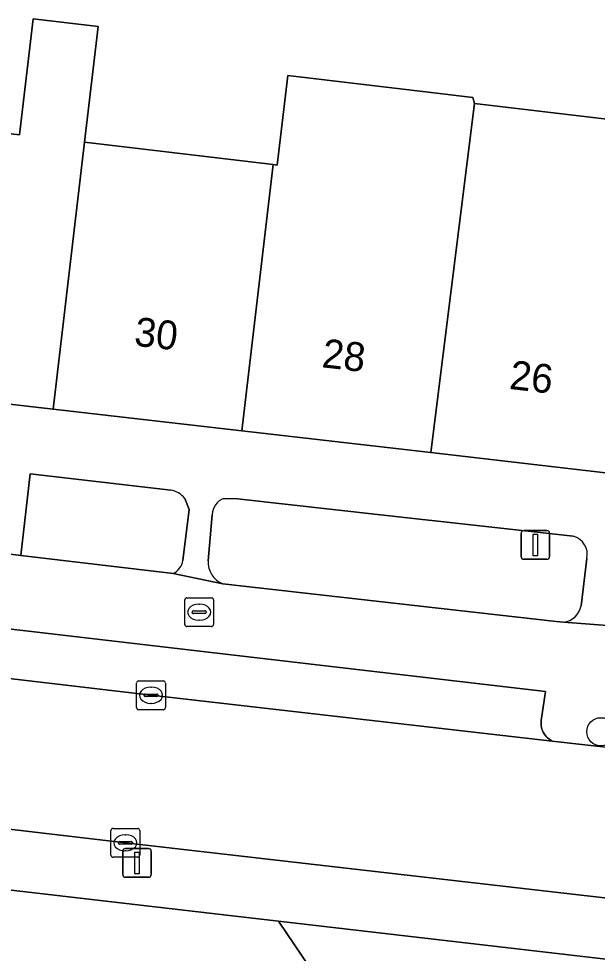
# Model space of a CAD drawing. Extents: x 161692 to 162379, y 380760 to 381678.
# Drawn here: x 162153.91 to 162173.98, y 380911.1 to 380943.5 of the extents above; entities that cross this region are included whole.
import ezdxf

# ---------------------------------------------------------------- set-up
doc = ezdxf.new("R2010")
doc.units = 0
for name, color, linetype in [('IMGEO_Boom', 7, 'Continuous'), ('IMGEO_Erf', 7, 'Continuous'), ('IMGEO_Groenvoorziening', 7, 'Continuous'), ('IMGEO_Kolk', 7, 'Continuous'), ('IMGEO_Lichtmast', 7, 'Continuous'), ('IMGEO_Pand', 7, 'Continuous'), ('IMGEO_Pand_nummerreeks', 7, 'Continuous'), ('IMGEO_Parkeervlak_open', 7, 'Continuous'), ('IMGEO_Rijbaan_lokaal_open', 7, 'Continuous'), ('IMGEO_Rioolput', 7, 'Continuous'), ('IMGEO_Voetpad_open', 7, 'Continuous')]:
    doc.layers.add(name, color=color, linetype=linetype)

msp = doc.modelspace()

# ---------------------------------------------------------------- linework, layer by layer
at = {"layer": 'IMGEO_Boom'}
msp.add_circle((162174.101, 380918.781), 0.489, dxfattribs=at)
at = {"layer": 'IMGEO_Erf'}
msp.add_lwpolyline([(162149.749, 380939.976), (162153.942, 380939.481), (162154.414, 380943.502), (162156.661, 380943.237), (162156.19, 380939.216), (162162.732, 380938.443), (162162.879, 380938.426), (162163.245, 380941.527), (162168.211, 380940.941), (162169.663, 380940.77), (162169.722, 380940.558), (162176.175, 380939.797), (162176.102, 380939.161), (162180.326, 380938.663), (162180.07, 380936.433), (162182.082, 380936.203), (162182.337, 380938.426), (162182.537, 380940.116), (162189.348, 380939.336), (162195.488, 380938.633), (162195.532, 380939.009), (162195.906, 380938.966), (162196.729, 380938.872), (162202.378, 380938.225)], dxfattribs=at)
at = {"layer": 'IMGEO_Groenvoorziening'}
for points in [[(162159.191, 380927.157), (162154.306, 380927.722), (162153.979, 380924.897), (162159.272, 380924.264)], [(162159.824, 380926.485), (162159.671, 380926.871)], [(162173.145, 380925.558), (162166.566, 380926.294), (162161.497, 380926.854), (162161.027, 380926.872)], [(162159.608, 380924.721), (162159.824, 380926.485)], [(162160.624, 380926.307), (162160.485, 380924.708)], [(162173.419, 380923.148), (162173.614, 380924.784)], [(162160.992, 380923.909), (162172.549, 380922.602), (162172.806, 380922.582)], [(162179.111, 380876.785), (162181.716, 380899.182), (162170.889, 380900.442), (162162.923, 380912.217), (162130.514, 380915.971), (162126.267, 380878.692), (162126.199, 380878.375), (162131.289, 380877.654), (162145.584, 380875.831), (162156.037, 380874.407), (162163.634, 380873.357), (162172.879, 380872.08)], [(162176.671, 380910.624), (162162.923, 380912.217), (162170.889, 380900.442), (162181.716, 380899.182), (162182.348, 380904.613), (162180.846, 380904.754), (162180.998, 380906.358)]]:
    msp.add_lwpolyline(points, dxfattribs=at)
for centre, radius, start, end in [((162159.064, 380926.398), 0.77, 37.9348, 80.4894), ((162161.244, 380926.291), 0.62, 110.4868, 178.5146), ((162172.986, 380924.933), 0.645, 346.674, 75.7529), ((162158.962, 380924.844), 0.658, 298.1306, 349.2205), ((162161.285, 380924.656), 0.802, 176.2529, 248.5409), ((162172.731, 380923.278), 0.7, 276.1575, 349.2768)]:
    msp.add_arc(centre, radius, start, end, dxfattribs=at)
at = {"layer": 'IMGEO_Kolk'}
for p, q in [((162158, 380919.62), (162158, 380920.472)), ((162158.075, 380920.546), (162158.927, 380920.546)), ((162159.001, 380920.472), (162159.001, 380919.62)), ((162158.302, 380920.089), (162158.7, 380920.089)), ((162158.488, 380920.326), (162158.513, 380920.326)), ((162158.259, 380920.04), (162158.259, 380920.052)), ((162158.697, 380920.003), (162158.299, 380920.003)), ((162158.511, 380919.766), (162158.486, 380919.766)), ((162158.743, 380920.052), (162158.743, 380920.04)), ((162158.927, 380919.546), (162158.075, 380919.546)), ((162157.11, 380914.505), (162157.11, 380915.357)), ((162157.185, 380915.431), (162158.037, 380915.431)), ((162157.598, 380915.211), (162157.623, 380915.211)), ((162158.111, 380915.357), (162158.111, 380914.505)), ((162157.369, 380914.925), (162157.369, 380914.937)), ((162157.807, 380914.888), (162157.409, 380914.888)), ((162157.412, 380914.974), (162157.81, 380914.974)), ((162157.853, 380914.937), (162157.853, 380914.925)), ((162157.621, 380914.651), (162157.596, 380914.651)), ((162158.037, 380914.431), (162157.185, 380914.431))]:
    msp.add_line(p, q, dxfattribs=at)
for points in [[(162158, 380919.62), (162158, 380920.472)], [(162158.075, 380920.546), (162158.927, 380920.546)], [(162159.001, 380920.472), (162159.001, 380919.62)], [(162158.927, 380919.546), (162158.075, 380919.546)], [(162157.11, 380914.505), (162157.11, 380915.357)], [(162157.185, 380915.431), (162158.037, 380915.431)], [(162158.111, 380915.357), (162158.111, 380914.505)], [(162158.037, 380914.431), (162157.185, 380914.431)]]:
    msp.add_lwpolyline(points, dxfattribs=at)
for centre, radius, start, end in [((162158.077, 380920.47), 0.0765, 91.552, 178.448), ((162158.077, 380920.47), 0.0765, 91.552, 178.448), ((162158.925, 380920.47), 0.0765, 1.552, 88.448), ((162158.925, 380920.47), 0.0765, 1.552, 88.448), ((162158.299, 380920.049), 0.0403, 85.8775, 175.7526), ((162158.704, 380920.051), 0.0386, 1.7309, 96.639), ((162158.296, 380920.039), 0.0366, 178.938, 274.7102), ((162158.7, 380920.046), 0.043, 264.8664, 352.4533), ((162158.077, 380919.622), 0.0765, 181.552, 268.448), ((162158.077, 380919.622), 0.0765, 181.552, 268.448), ((162158.925, 380919.622), 0.0765, 271.552, 358.448), ((162158.925, 380919.622), 0.0765, 271.552, 358.448), ((162157.187, 380915.355), 0.0765, 91.552, 178.448), ((162157.187, 380915.355), 0.0765, 91.552, 178.448), ((162158.035, 380915.355), 0.0765, 1.552, 88.448), ((162158.035, 380915.355), 0.0765, 1.552, 88.448), ((162157.409, 380914.934), 0.0403, 85.8775, 175.7526), ((162157.406, 380914.924), 0.0366, 178.938, 274.7102), ((162157.81, 380914.931), 0.043, 264.8664, 352.4533), ((162157.814, 380914.936), 0.0386, 1.7309, 96.639), ((162157.187, 380914.507), 0.0765, 181.552, 268.448), ((162157.187, 380914.507), 0.0765, 181.552, 268.448), ((162158.035, 380914.507), 0.0765, 271.552, 358.448), ((162158.035, 380914.507), 0.0765, 271.552, 358.448)]:
    msp.add_arc(centre, radius, start, end, dxfattribs=at)
for centre, major_axis, ratio, start_param, end_param in [((162158.487, 380920.046), (-0.387, 0.002), 0.722429, 4.712389, 7.853982), ((162158.512, 380920.046), (-0.39, 0.002), 0.717154, 1.570796, 4.712389), ((162157.597, 380914.931), (-0.387, 0.002), 0.722429, 4.712389, 7.853982), ((162157.622, 380914.931), (-0.39, 0.002), 0.717154, 1.570796, 4.712389)]:
    msp.add_ellipse(centre, major_axis=major_axis, ratio=ratio, start_param=start_param, end_param=end_param, dxfattribs=at)
at = {"layer": 'IMGEO_Lichtmast'}
for p, q in [((162171.334, 380924.86), (162171.334, 380925.66)), ((162171.334, 380925.66), (162171.334, 380924.86)), ((162171.434, 380925.76), (162172.224, 380925.76)), ((162172.224, 380925.76), (162171.434, 380925.76)), ((162172.324, 380925.66), (162172.324, 380924.86)), ((162172.324, 380924.86), (162172.324, 380925.66)), ((162172.224, 380924.76), (162171.434, 380924.76)), ((162171.434, 380924.76), (162172.224, 380924.76)), ((162157.519, 380913.835), (162157.519, 380914.635)), ((162157.519, 380914.635), (162157.519, 380913.835)), ((162157.619, 380914.735), (162158.409, 380914.735)), ((162158.409, 380914.735), (162157.619, 380914.735)), ((162158.509, 380914.635), (162158.509, 380913.835)), ((162158.509, 380913.835), (162158.509, 380914.635)), ((162158.409, 380913.735), (162157.619, 380913.735)), ((162157.619, 380913.735), (162158.409, 380913.735))]:
    msp.add_line(p, q, dxfattribs=at)
for points in [[(162171.754, 380925.635), (162171.904, 380925.635), (162171.904, 380924.885), (162171.754, 380924.885), (162171.754, 380925.635)], [(162157.939, 380914.61), (162158.089, 380914.61), (162158.089, 380913.86), (162157.939, 380913.86), (162157.939, 380914.61)]]:
    msp.add_lwpolyline(points, dxfattribs=at)
for centre, start, end in [((162171.434, 380925.66), 90, 180), ((162171.434, 380925.66), 90, 180), ((162172.224, 380925.66), 0, 90), ((162172.224, 380925.66), 360, 90), ((162171.434, 380924.86), 180, 270), ((162171.434, 380924.86), 180, 270), ((162172.224, 380924.86), 270, 0), ((162172.224, 380924.86), 270, 0), ((162157.619, 380914.635), 90, 180), ((162157.619, 380914.635), 90, 180), ((162158.409, 380914.635), 0, 90), ((162158.409, 380914.635), 360, 90), ((162157.619, 380913.835), 180, 270), ((162157.619, 380913.835), 180, 270), ((162158.409, 380913.835), 270, 0), ((162158.409, 380913.835), 270, 0)]:
    msp.add_arc(centre, 0.1, start, end, dxfattribs=at)
at = {"layer": 'IMGEO_Pand'}
for points in [[(162156.19, 380939.216), (162156.661, 380943.237), (162154.414, 380943.502), (162153.942, 380939.481), (162149.749, 380939.976), (162149.553, 380938.318), (162146.545, 380938.673), (162145.84, 380932.694), (162148.848, 380932.339), (162148.655, 380930.7), (162155.105, 380929.962)], [(162161.646, 380929.214), (162168.105, 380928.475), (162168.21, 380928.463), (162169.722, 380940.558), (162169.663, 380940.77), (162168.211, 380940.941), (162163.245, 380941.527), (162162.879, 380938.426), (162162.732, 380938.443)], [(162176.102, 380939.161), (162176.175, 380939.797), (162169.722, 380940.558), (162168.21, 380928.463), (162174.757, 380927.705)], [(162162.732, 380938.443), (162156.19, 380939.216), (162155.105, 380929.962), (162161.646, 380929.214)]]:
    msp.add_lwpolyline(points, close=True, dxfattribs=at)
at = {"layer": 'IMGEO_Parkeervlak_open'}
msp.add_lwpolyline([(162144.319, 380921.71), (162158.501, 380920.045), (162172.418, 380918.461), (162172.394, 380918.473), (162172.342, 380918.503), (162172.292, 380918.537), (162172.246, 380918.575), (162172.204, 380918.618), (162172.166, 380918.664), (162172.132, 380918.713), (162172.102, 380918.766), (162172.077, 380918.82), (162172.057, 380918.877), (162172.043, 380918.935), (162172.033, 380918.994), (162172.029, 380919.054), (162172.03, 380919.114), (162172.037, 380919.174), (162172.178, 380920.182), (162144.831, 380923.365)], dxfattribs=at)
at = {"layer": 'IMGEO_Rijbaan_lokaal_open'}
for points in [[(162194.36, 380915.961), (162175.911, 380918.063), (162172.418, 380918.461), (162158.501, 380920.045), (162144.319, 380921.71)], [(162140.919, 380916.892), (162157.612, 380914.932), (162177.053, 380912.703), (162177.833, 380912.69), (162193.581, 380910.917), (162194.485, 380910.711), (162194.716, 380910.676), (162208.277, 380908.928), (162208.7, 380908.873), (162217.892, 380907.916), (162227.216, 380906.767), (162227.782, 380906.697), (162234.526, 380905.958), (162239.433, 380906.183), (162250.003, 380907.94), (162251.002, 380908.119), (162251.25, 380908.148), (162253.265, 380908.282), (162255.284, 380908.236), (162255.857, 380913.38), (162254.116, 380913.492)]]:
    msp.add_lwpolyline(points, dxfattribs=at)
at = {"layer": 'IMGEO_Rioolput'}
for p, q in [((162159.67, 380922.501), (162159.67, 380923.353)), ((162159.745, 380923.427), (162160.597, 380923.427)), ((162160.671, 380923.353), (162160.671, 380922.501)), ((162160.158, 380923.207), (162160.183, 380923.207)), ((162159.929, 380922.921), (162159.929, 380922.933)), ((162160.367, 380922.884), (162159.969, 380922.884)), ((162159.972, 380922.97), (162160.37, 380922.97)), ((162160.413, 380922.933), (162160.413, 380922.921)), ((162160.597, 380922.427), (162159.745, 380922.427)), ((162160.181, 380922.647), (162160.156, 380922.647))]:
    msp.add_line(p, q, dxfattribs=at)
for points in [[(162159.67, 380922.501), (162159.67, 380923.353)], [(162159.745, 380923.427), (162160.597, 380923.427)], [(162160.671, 380923.353), (162160.671, 380922.501)], [(162160.597, 380922.427), (162159.745, 380922.427)]]:
    msp.add_lwpolyline(points, dxfattribs=at)
for centre, radius, start, end in [((162159.747, 380923.351), 0.0765, 91.552, 178.448), ((162159.747, 380923.351), 0.0765, 91.552, 178.448), ((162160.595, 380923.351), 0.0765, 1.552, 88.448), ((162160.595, 380923.351), 0.0765, 1.552, 88.448), ((162159.969, 380922.93), 0.0403, 85.8775, 175.7526), ((162159.966, 380922.92), 0.0366, 178.938, 274.7102), ((162160.37, 380922.927), 0.043, 264.8664, 352.4533), ((162160.374, 380922.932), 0.0386, 1.7309, 96.639), ((162159.747, 380922.503), 0.0765, 181.552, 268.448), ((162159.747, 380922.503), 0.0765, 181.552, 268.448), ((162160.595, 380922.503), 0.0765, 271.552, 358.448), ((162160.595, 380922.503), 0.0765, 271.552, 358.448)]:
    msp.add_arc(centre, radius, start, end, dxfattribs=at)
for centre, major_axis, ratio, start_param, end_param in [((162160.157, 380922.927), (-0.387, 0.002), 0.722429, 4.712389, 7.853982), ((162160.182, 380922.927), (-0.39, 0.002), 0.717154, 1.570796, 4.712389)]:
    msp.add_ellipse(centre, major_axis=major_axis, ratio=ratio, start_param=start_param, end_param=end_param, dxfattribs=at)
at = {"layer": 'IMGEO_Voetpad_open'}
for points in [[(162246.079, 380919.46), (162239.67, 380920.198), (162233.283, 380920.934), (162232.951, 380920.972), (162226.693, 380921.696), (162220.458, 380922.418), (162213.812, 380923.186), (162207.219, 380923.949), (162200.781, 380924.694), (162193.937, 380925.486), (162187.797, 380926.197), (162180.993, 380926.984), (162174.757, 380927.705), (162168.21, 380928.463), (162168.105, 380928.475), (162161.646, 380929.214), (162155.105, 380929.962), (162148.655, 380930.7), (162144.778, 380931.153)], [(162145.325, 380928.896), (162147.083, 380928.518), (162149.069, 380928.327), (162153.474, 380927.818), (162153.157, 380924.996), (162153.979, 380924.897), (162154.306, 380927.722), (162159.191, 380927.157)], [(162159.671, 380926.871), (162159.824, 380926.485), (162159.608, 380924.721)], [(162161.027, 380926.872), (162161.497, 380926.854), (162166.566, 380926.294), (162173.145, 380925.558)], [(162200.813, 380919.445), (162198.762, 380919.679), (162187.648, 380920.991), (162185.902, 380921.167), (162185.669, 380921.214), (162174.637, 380922.44), (162172.806, 380922.582), (162172.549, 380922.602), (162160.992, 380923.909), (162159.272, 380924.264), (162153.979, 380924.897), (162153.157, 380924.996), (162141.863, 380926.228), (162138.143, 380926.533), (162138.047, 380925.435)], [(162160.485, 380924.708), (162160.624, 380926.307)], [(162173.614, 380924.784), (162173.419, 380923.148)], [(162159.272, 380924.264), (162160.992, 380923.909)], [(162144.831, 380923.365), (162172.178, 380920.182), (162172.037, 380919.174), (162172.03, 380919.114), (162172.029, 380919.054), (162172.033, 380918.994), (162172.043, 380918.935), (162172.057, 380918.877), (162172.077, 380918.82), (162172.102, 380918.766), (162172.132, 380918.713), (162172.166, 380918.664), (162172.204, 380918.618), (162172.246, 380918.575), (162172.292, 380918.537), (162172.342, 380918.503), (162172.394, 380918.473), (162172.418, 380918.461), (162175.911, 380918.063)], [(162172.806, 380922.582), (162174.637, 380922.44)], [(162157.612, 380914.932), (162140.919, 380916.892), (162140.168, 380916.98), (162128.018, 380918.379), (162127.866, 380918.397), (162123.714, 380918.875)], [(162124.922, 380918.06), (162127.938, 380917.699), (162128.756, 380917.601), (162128.726, 380917.341), (162130.645, 380917.122), (162130.514, 380915.971), (162162.923, 380912.217), (162176.671, 380910.624)], [(162177.053, 380912.703), (162157.612, 380914.932)]]:
    msp.add_lwpolyline(points, dxfattribs=at)
for centre, radius, start, end in [((162159.064, 380926.398), 0.77, 37.9348, 80.4894), ((162161.244, 380926.291), 0.62, 110.4868, 178.5146), ((162172.986, 380924.933), 0.645, 346.674, 75.7529), ((162158.962, 380924.844), 0.658, 298.1306, 349.2205), ((162161.285, 380924.656), 0.802, 176.2529, 248.5409), ((162172.731, 380923.278), 0.7, 276.1575, 349.2768)]:
    msp.add_arc(centre, radius, start, end, dxfattribs=at)

# ---------------------------------------------------------------- texts
at = {"layer": 'IMGEO_Pand_nummerreeks'}
for s, p in [('30', (162157.889, 380932.172)), ('28', (162164.397, 380931.421)), ('26', (162170.902, 380930.67))]:
    msp.add_text(s, height=1, rotation=353.4197, dxfattribs=at).set_placement(p)

doc.saveas('drawing.dxf')
